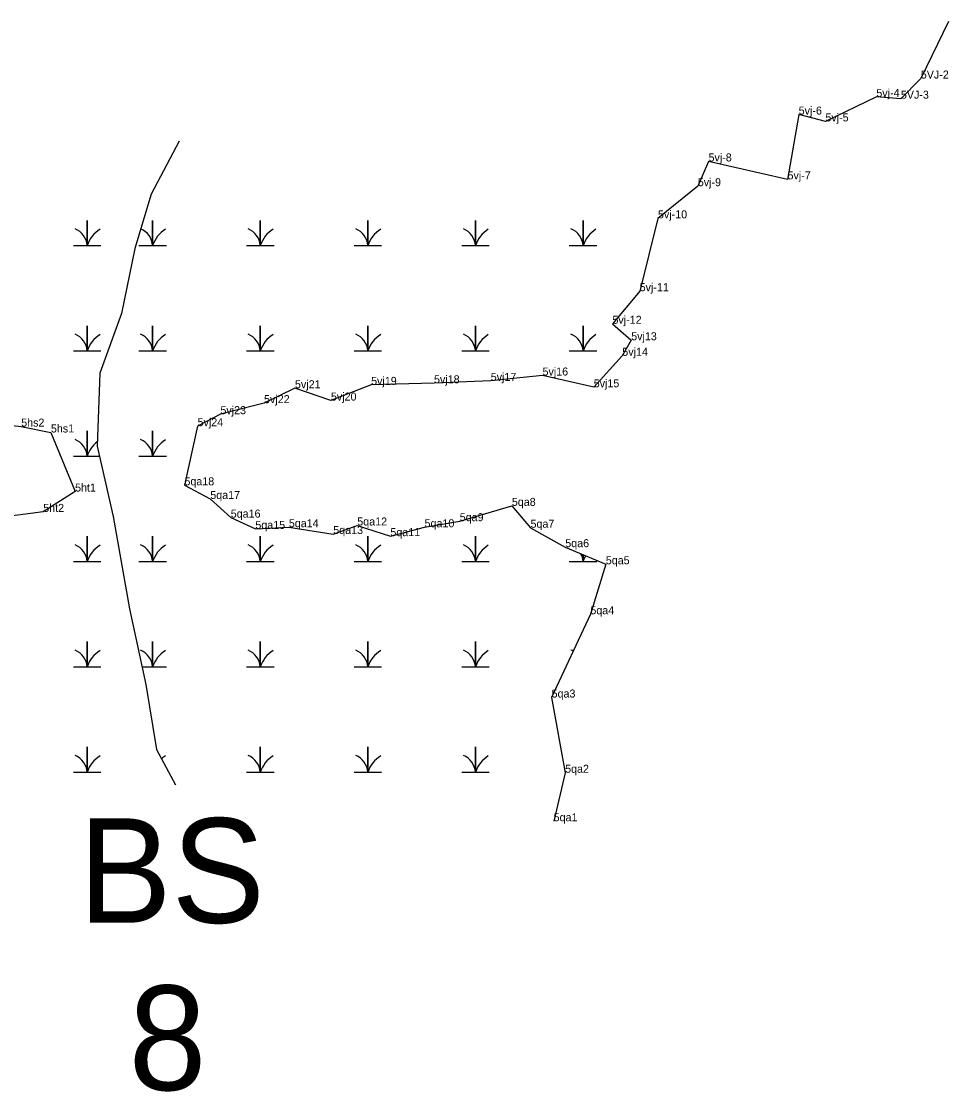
# Model space of a CAD drawing. Extents: x 2072529 to 2268796, y 436423 to 470406.
# Drawn here: x 2129175 to 2129755, y 446479 to 447148 of the extents above; entities that cross this region are included whole.
import ezdxf

# ---------------------------------------------------------------- set-up
doc = ezdxf.new("R2010")
doc.units = 0
for name, color, linetype in [('Default', 7, 'Continuous'), ('Exist Environmental Wetland Boundary Cogo Comment', 7, 'Continuous'), ('Exist Environmental Wetland Boundary Cogo Point CELL', 7, 'Continuous'), ('Old_Level_20', 7, 'Continuous'), ('Old_Level_52', 7, 'Continuous')]:
    doc.layers.add(name, color=color, linetype=linetype)

msp = doc.modelspace()

# ---------------------------------------------------------------- linework, layer by layer
at = {"layer": 'Exist Environmental Wetland Boundary Cogo Point CELL'}
for points in [[(2129207.63, 447007.45), (2129216.23, 447007.45), (2129216.23, 447023.23), (2129216.23, 447007.45), (2129224.83, 447007.45)], [(2129248.53, 447007.45), (2129257.14, 447007.45), (2129257.14, 447023.23), (2129257.14, 447007.45), (2129265.74, 447007.45)], [(2129315.78, 447007.45), (2129324.39, 447007.45), (2129324.39, 447023.23), (2129324.39, 447007.45), (2129332.99, 447007.45)], [(2129383.03, 447007.45), (2129391.64, 447007.45), (2129391.64, 447023.23), (2129391.64, 447007.45), (2129400.24, 447007.45)], [(2129450.28, 447007.45), (2129458.89, 447007.45), (2129458.89, 447023.23), (2129458.89, 447007.45), (2129467.49, 447007.45)], [(2129517.53, 447007.45), (2129526.14, 447007.45), (2129526.14, 447023.23), (2129526.14, 447007.45), (2129534.74, 447007.45)], [(2129207.63, 446941.65), (2129216.23, 446941.65), (2129216.23, 446957.43), (2129216.23, 446941.65), (2129224.83, 446941.65)], [(2129248.53, 446941.65), (2129257.14, 446941.65), (2129257.14, 446957.43), (2129257.14, 446941.65), (2129265.74, 446941.65)], [(2129315.78, 446941.65), (2129324.39, 446941.65), (2129324.39, 446957.43), (2129324.39, 446941.65), (2129332.99, 446941.65)], [(2129383.03, 446941.65), (2129391.64, 446941.65), (2129391.64, 446957.43), (2129391.64, 446941.65), (2129400.24, 446941.65)], [(2129450.28, 446941.65), (2129458.89, 446941.65), (2129458.89, 446957.43), (2129458.89, 446941.65), (2129467.49, 446941.65)], [(2129517.53, 446941.65), (2129526.14, 446941.65), (2129526.14, 446957.43), (2129526.14, 446941.65), (2129534.74, 446941.65)], [(2129207.63, 446875.85), (2129216.23, 446875.85), (2129216.23, 446891.63), (2129216.23, 446875.85), (2129223.86, 446875.85)], [(2129248.53, 446875.85), (2129257.14, 446875.85), (2129257.14, 446891.63), (2129257.14, 446875.85), (2129265.74, 446875.85)], [(2129207.63, 446810.05), (2129216.23, 446810.05), (2129216.23, 446825.83), (2129216.23, 446810.05), (2129224.83, 446810.05)], [(2129248.53, 446810.05), (2129257.14, 446810.05), (2129257.14, 446825.83), (2129257.14, 446810.05), (2129265.74, 446810.05)], [(2129315.78, 446810.05), (2129324.39, 446810.05), (2129324.39, 446825.83), (2129324.39, 446810.05), (2129332.99, 446810.05)], [(2129383.03, 446810.05), (2129391.64, 446810.05), (2129391.64, 446825.83), (2129391.64, 446810.05), (2129400.24, 446810.05)], [(2129450.28, 446810.05), (2129458.89, 446810.05), (2129458.89, 446825.83), (2129458.89, 446810.05), (2129467.49, 446810.05)], [(2129517.53, 446810.05), (2129526.14, 446810.05), (2129526.14, 446814.34)], [(2129526.14, 446814.34), (2129526.14, 446810.05), (2129534.74, 446810.05)], [(2129207.63, 446744.25), (2129216.23, 446744.25), (2129216.23, 446760.03), (2129216.23, 446744.25), (2129224.83, 446744.25)], [(2129250.49, 446744.25), (2129257.14, 446744.25), (2129257.14, 446760.03), (2129257.14, 446744.25), (2129265.74, 446744.25)], [(2129315.78, 446744.25), (2129324.39, 446744.25), (2129324.39, 446760.03), (2129324.39, 446744.25), (2129332.99, 446744.25)], [(2129383.03, 446744.25), (2129391.64, 446744.25), (2129391.64, 446760.03), (2129391.64, 446744.25), (2129400.24, 446744.25)], [(2129450.28, 446744.25), (2129458.89, 446744.25), (2129458.89, 446760.03), (2129458.89, 446744.25), (2129467.49, 446744.25)], [(2129207.63, 446678.45), (2129216.23, 446678.45), (2129216.23, 446694.23), (2129216.23, 446678.45), (2129224.83, 446678.45)], [(2129315.78, 446678.45), (2129324.39, 446678.45), (2129324.39, 446694.23), (2129324.39, 446678.45), (2129332.99, 446678.45)], [(2129383.03, 446678.45), (2129391.64, 446678.45), (2129391.64, 446694.23), (2129391.64, 446678.45), (2129400.24, 446678.45)], [(2129450.28, 446678.45), (2129458.89, 446678.45), (2129458.89, 446694.23), (2129458.89, 446678.45), (2129467.49, 446678.45)]]:
    msp.add_lwpolyline(points, dxfattribs=at)
for centre, radius, start, end in [((2129203.96, 447006.56), 12.3, 4.14034, 67.53497), ((2129234.47, 447001.39), 19.22, 122.12745, 161.62219), ((2129244.87, 447006.56), 12.3, 4.14034, 66.67465), ((2129275.38, 447001.39), 19.22, 122.12745, 161.62219), ((2129312.12, 447006.56), 12.3, 4.14034, 67.53497), ((2129342.63, 447001.39), 19.22, 122.12745, 161.62219), ((2129379.37, 447006.56), 12.3, 4.14034, 67.53497), ((2129409.88, 447001.39), 19.22, 122.12745, 161.62219), ((2129446.62, 447006.56), 12.3, 4.14034, 67.53497), ((2129477.13, 447001.39), 19.22, 122.12745, 161.62219), ((2129513.87, 447006.56), 12.3, 4.14034, 67.53497), ((2129544.38, 447001.39), 19.22, 122.12745, 161.62219), ((2129203.96, 446940.76), 12.3, 4.14034, 67.53497), ((2129234.47, 446935.59), 19.22, 122.12745, 161.62219), ((2129244.87, 446940.76), 12.3, 4.14034, 67.53497), ((2129275.38, 446935.59), 19.22, 122.12745, 161.62219), ((2129312.12, 446940.76), 12.3, 4.14034, 67.53497), ((2129342.63, 446935.59), 19.22, 122.12745, 161.62219), ((2129379.37, 446940.76), 12.3, 4.14034, 67.53497), ((2129409.88, 446935.59), 19.22, 122.12745, 161.62219), ((2129446.62, 446940.76), 12.3, 4.14034, 67.53497), ((2129477.13, 446935.59), 19.22, 122.12745, 161.62219), ((2129513.87, 446940.76), 12.3, 4.14034, 67.53497), ((2129544.38, 446935.59), 19.22, 122.12745, 161.62219), ((2129203.96, 446874.96), 12.3, 4.14034, 67.53497), ((2129234.47, 446869.79), 19.22, 128.47685, 161.62219), ((2129244.87, 446874.96), 12.3, 4.14034, 67.53497), ((2129275.38, 446869.79), 19.22, 122.12745, 161.62219), ((2129203.96, 446809.16), 12.3, 4.14034, 67.53497), ((2129234.47, 446803.99), 19.22, 122.12745, 161.62219), ((2129244.87, 446809.16), 12.3, 4.14034, 67.53497), ((2129275.38, 446803.99), 19.22, 122.12745, 161.62219), ((2129312.12, 446809.16), 12.3, 4.14034, 67.53497), ((2129342.63, 446803.99), 19.22, 122.12745, 161.62219), ((2129379.37, 446809.16), 12.3, 4.14034, 67.53497), ((2129409.88, 446803.99), 19.22, 122.12745, 161.62219), ((2129446.62, 446809.16), 12.3, 4.14034, 67.53497), ((2129477.13, 446803.99), 19.22, 122.12745, 161.62219), ((2129513.87, 446809.16), 12.3, 4.14034, 28.04598), ((2129544.38, 446803.99), 19.22, 149.79905, 161.62219), ((2129203.96, 446743.36), 12.3, 4.14034, 67.53497), ((2129234.47, 446738.19), 19.22, 122.12745, 161.62219), ((2129244.87, 446743.36), 12.3, 4.14034, 67.53497), ((2129275.38, 446738.19), 19.22, 122.12745, 161.62219), ((2129312.12, 446743.36), 12.3, 4.14034, 67.53497), ((2129342.63, 446738.19), 19.22, 122.12745, 161.62219), ((2129379.37, 446743.36), 12.3, 4.14034, 67.53497), ((2129409.88, 446738.19), 19.22, 122.12745, 161.62219), ((2129446.62, 446743.36), 12.3, 4.14034, 67.53497), ((2129477.13, 446738.19), 19.22, 122.12745, 161.62219), ((2129513.87, 446743.36), 12.3, 60.29855, 67.53497), ((2129203.96, 446677.56), 12.3, 4.14034, 67.53497), ((2129234.47, 446672.39), 19.22, 122.12745, 161.62219), ((2129275.38, 446672.39), 19.22, 122.12745, 131.21059), ((2129312.12, 446677.56), 12.3, 4.14034, 67.53497), ((2129342.63, 446672.39), 19.22, 122.12745, 161.62219), ((2129379.37, 446677.56), 12.3, 4.14034, 67.53497), ((2129409.88, 446672.39), 19.22, 122.12745, 161.62219), ((2129446.62, 446677.56), 12.3, 4.14034, 67.53497), ((2129477.13, 446672.39), 19.22, 122.12745, 161.62219)]:
    msp.add_arc(centre, radius, start, end, dxfattribs=at)
at = {"layer": 'Old_Level_20'}
for p, q in [((2129754.55, 447147.54), (2129754.55, 447147.54)), ((2129737.2, 447111.83), (2129737.2, 447111.83)), ((2129709.41, 447100.35), (2129709.41, 447100.35)), ((2129724.75, 447099.25), (2129724.75, 447099.25)), ((2129660.88, 447089.32), (2129660.88, 447089.32)), ((2129677.58, 447085.05), (2129677.58, 447085.05)), ((2129604.54, 447060.04), (2129604.54, 447060.04)), ((2129597.83, 447044.57), (2129597.83, 447044.57)), ((2129653.9, 447048.83), (2129653.9, 447048.83)), ((2129572.94, 447024.49), (2129572.94, 447024.49)), ((2129561.5, 446978.99), (2129561.5, 446978.99)), ((2129544.48, 446958.61), (2129544.48, 446958.61)), ((2129556.2, 446948.32), (2129556.2, 446948.32)), ((2129550.65, 446938.6), (2129550.65, 446938.6)), ((2129468.43, 446922.93), (2129468.43, 446922.93)), ((2129500.78, 446926.28), (2129500.78, 446926.28)), ((2129346.1, 446918.34), (2129346.1, 446918.34)), ((2129393.68, 446920.42), (2129393.68, 446920.42)), ((2129432.99, 446921.43), (2129432.99, 446921.43)), ((2129532.79, 446918.92), (2129532.79, 446918.92)), ((2129368.55, 446910.64), (2129368.55, 446910.64)), ((2129326.75, 446909.02), (2129326.75, 446909.02)), ((2129299.5, 446902.13), (2129299.5, 446902.13)), ((2129193.56, 446890.7), (2129193.56, 446890.7)), ((2129285.23, 446894.64), (2129285.23, 446894.64)), ((2129277.02, 446857.68), (2129277.02, 446857.68)), ((2129208.67, 446853.77), (2129208.67, 446853.77)), ((2129293.18, 446849.14), (2129293.18, 446849.14)), ((2129481.64, 446844.84), (2129481.64, 446844.84)), ((2129188.76, 446841.08), (2129188.76, 446841.08)), ((2129305.96, 446837.51), (2129305.96, 446837.51)), ((2129321.34, 446830.44), (2129321.34, 446830.44)), ((2129342.26, 446831.52), (2129342.26, 446831.52)), ((2129385.03, 446832.59), (2129385.03, 446832.59)), ((2129427.08, 446831.46), (2129427.08, 446831.46)), ((2129449.05, 446835.28), (2129449.05, 446835.28)), ((2129493.29, 446831.18), (2129493.29, 446831.18)), ((2129370.02, 446827.24), (2129370.02, 446827.24)), ((2129405.71, 446825.92), (2129405.71, 446825.92)), ((2129515.01, 446819.04), (2129515.01, 446819.04)), ((2129540.34, 446808.34), (2129540.34, 446808.34)), ((2129530.7, 446777.11), (2129530.7, 446777.11)), ((2129506.48, 446725.08), (2129506.48, 446725.08)), ((2129514.9, 446678.09), (2129514.9, 446678.09)), ((2129507.75, 446647.78), (2129507.75, 446647.78))]:
    msp.add_line(p, q, dxfattribs=at)
for points in [[(2129754.55, 447147.54), (2129737.2, 447111.83), (2129724.75, 447099.25), (2129709.41, 447100.35), (2129677.58, 447085.05), (2129660.88, 447089.32), (2129653.9, 447048.83), (2129604.54, 447060.04), (2129597.83, 447044.57), (2129572.94, 447024.49), (2129561.5, 446978.99), (2129544.48, 446958.61), (2129556.2, 446948.32), (2129550.65, 446938.6), (2129532.79, 446918.92), (2129500.78, 446926.28), (2129468.43, 446922.93), (2129432.99, 446921.43), (2129393.68, 446920.42), (2129368.55, 446910.64), (2129346.1, 446918.34), (2129326.75, 446909.02), (2129299.5, 446902.13), (2129285.23, 446894.64), (2129277.02, 446857.68)], [(2128812.94, 447112.63), (2128799.79, 447103.19), (2128803.63, 447058.88), (2128764.08, 447036.66), (2128710.11, 447017.7), (2128677.65, 446989.62), (2128674.94, 446964.41), (2128675.68, 446947.81), (2128680.21, 446926.61), (2128685.36, 446896.48), (2128796.7, 446898.71), (2128868.17, 446902.03), (2129065.12, 446907.49), (2129090.49, 446900.26), (2129117.47, 446901.52), (2129146.95, 446897.48), (2129174.99, 446894.38), (2129193.56, 446890.7), (2129208.67, 446853.77)], [(2129277.02, 446857.68), (2129293.18, 446849.14), (2129305.96, 446837.51), (2129321.34, 446830.44), (2129342.26, 446831.52), (2129370.02, 446827.24), (2129385.03, 446832.59), (2129405.71, 446825.92), (2129427.08, 446831.46), (2129449.05, 446835.28), (2129481.64, 446844.84), (2129493.29, 446831.18), (2129515.01, 446819.04), (2129540.34, 446808.34), (2129530.7, 446777.11), (2129506.48, 446725.08), (2129514.9, 446678.09), (2129507.75, 446647.78)], [(2129208.67, 446853.77), (2129188.76, 446841.08), (2129131.38, 446833.65), (2129070.71, 446832.53), (2129011.64, 446828.09), (2128971.9, 446825.85), (2128899.42, 446829.09), (2128796.85, 446830.79), (2128744.02, 446825.45), (2128712.14, 446788.81), (2128694.33, 446768.88), (2128678.5, 446731.96), (2128647.28, 446692.91), (2128665.62, 446640.75), (2128682.39, 446604.17), (2128710.82, 446634.39), (2128721.77, 446651.85), (2128758.18, 446674.04), (2128754.74, 446610.14), (2128745.62, 446568.66)]]:
    msp.add_lwpolyline(points, dxfattribs=at)
at = {"layer": 'Old_Level_52'}
msp.add_lwpolyline([(2129273.68, 447072.67), (2129256.23, 447039.51), (2129246.09, 447005.66), (2129237.63, 446965.05), (2129224.1, 446927.82), (2129222.41, 446882.13), (2129232.56, 446838.14), (2129242.7, 446780.6), (2129252.85, 446733.22), (2129259.61, 446692.61), (2129271.45, 446670.61)], dxfattribs=at)

# ---------------------------------------------------------------- texts
at = {"layer": 'Default'}
for s, p in [('BS', (2129210.73, 446584.35)), ('8', (2129242.15, 446479.81))]:
    msp.add_text(s, height=65.34, dxfattribs=at).set_placement(p)
at = {"layer": 'Exist Environmental Wetland Boundary Cogo Comment'}
for s, p in [('5VJ-2', (2129737.2, 447111.83)), ('5vj-4', (2129709.41, 447100.35)), ('5VJ-3', (2129724.75, 447099.25)), ('5vj-6', (2129660.88, 447089.32)), ('5vj-5', (2129677.58, 447085.05)), ('5vj-8', (2129604.54, 447060.04)), ('5vj-9', (2129597.83, 447044.57)), ('5vj-7', (2129653.9, 447048.83)), ('5vj-10', (2129572.94, 447024.49)), ('5vj-11', (2129561.5, 446978.99)), ('5vj-12', (2129544.48, 446958.61)), ('5vj13', (2129556.2, 446948.32)), ('5vj14', (2129550.65, 446938.6)), ('5vj16', (2129500.78, 446926.28)), ('5vj21', (2129346.1, 446918.34)), ('5vj19', (2129393.68, 446920.42)), ('5vj18', (2129432.99, 446921.43)), ('5vj17', (2129468.43, 446922.93)), ('5vj15', (2129532.79, 446918.92)), ('5vj22', (2129326.75, 446909.02)), ('5vj20', (2129368.55, 446910.64)), ('5vj23', (2129299.5, 446902.13)), ('5hs2', (2129174.99, 446894.38)), ('5hs1', (2129193.56, 446890.7)), ('5vj24', (2129285.23, 446894.64)), ('5qa18', (2129277.02, 446857.68)), ('5ht1', (2129208.67, 446853.77)), ('5qa17', (2129293.18, 446849.14)), ('5qa8', (2129481.64, 446844.84)), ('5ht2', (2129188.76, 446841.08)), ('5qa16', (2129305.96, 446837.51)), ('5qa14', (2129342.26, 446831.52)), ('5qa12', (2129385.03, 446832.59)), ('5qa10', (2129427.08, 446831.46)), ('5qa9', (2129449.05, 446835.28)), ('5qa7', (2129493.29, 446831.18)), ('5qa15', (2129321.34, 446830.44)), ('5qa13', (2129370.02, 446827.24)), ('5qa11', (2129405.71, 446825.92)), ('5qa6', (2129515.01, 446819.04)), ('5qa5', (2129540.34, 446808.34)), ('5qa4', (2129530.7, 446777.11)), ('5qa3', (2129506.48, 446725.08)), ('5qa2', (2129514.9, 446678.09)), ('5qa1', (2129507.75, 446647.78))]:
    msp.add_text(s, height=5, dxfattribs=at).set_placement(p)

doc.saveas('drawing.dxf')
